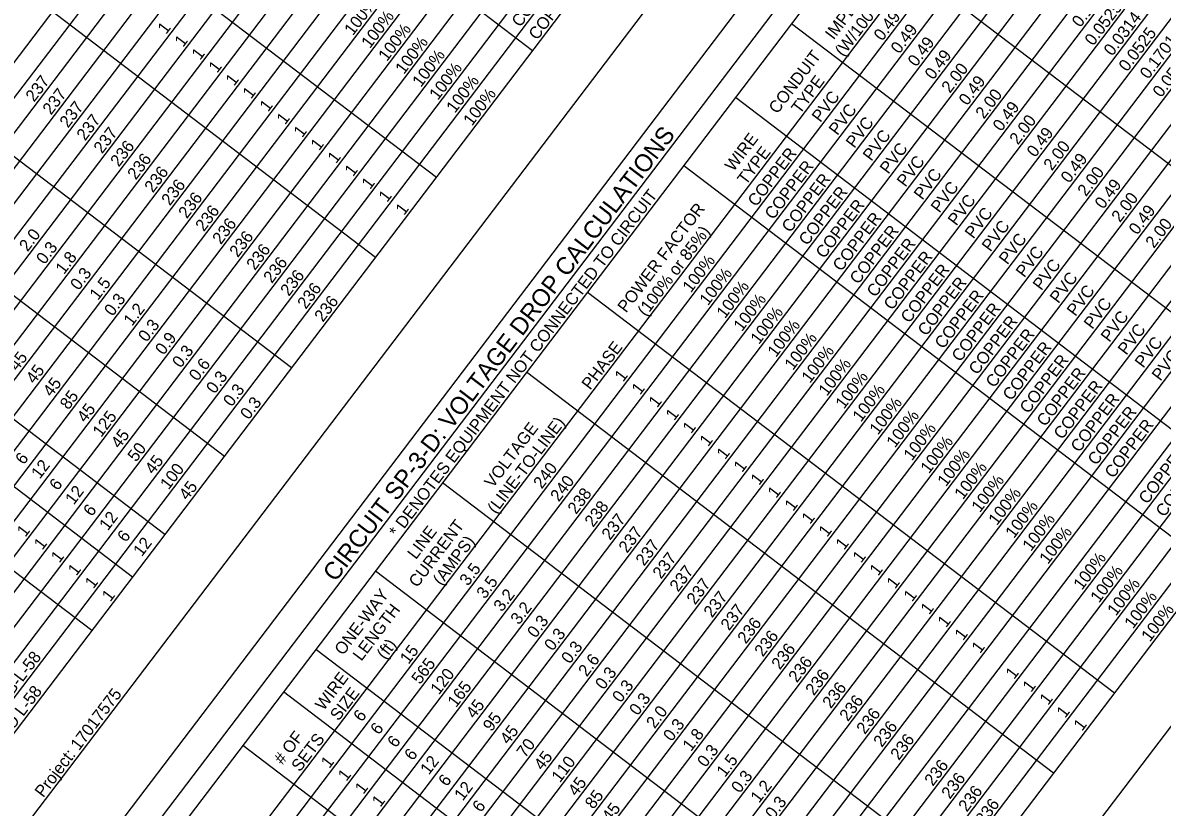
# Model space of a CAD drawing. Extents: x 1289840 to 1300285, y 220865 to 232461.
# Drawn here: x 1299156 to 1299781, y 231315 to 231745 of the extents above; entities that cross this region are included whole.
import ezdxf

# ---------------------------------------------------------------- set-up
doc = ezdxf.new("R2010")
doc.units = 0
doc.layers.add('Default', color=7, linetype='Continuous')

msp = doc.modelspace()

# ---------------------------------------------------------------- linework, layer by layer
at = {"layer": 'Default'}
for p, q in [((1298922.85, 231421.89), (1299441.25, 232103.62)), ((1298932.16, 231414.81), (1299450.56, 232096.54)), ((1298941.48, 231407.73), (1299459.87, 232089.46)), ((1298950.79, 231400.64), (1299469.19, 232082.37)), ((1298960.1, 231393.56), (1299478.5, 232075.29)), ((1298969.42, 231386.48), (1299487.81, 232068.21)), ((1298978.73, 231379.4), (1299497.13, 232061.13)), ((1298988.04, 231372.32), (1299506.44, 232054.05)), ((1298997.36, 231365.24), (1299515.75, 232046.96)), ((1299006.67, 231358.15), (1299525.07, 232039.88)), ((1299015.98, 231351.07), (1299534.38, 232032.8)), ((1299025.3, 231343.99), (1299543.69, 232025.72)), ((1299034.61, 231336.91), (1299553.01, 232018.64)), ((1299043.92, 231329.83), (1299562.32, 232011.55)), ((1299053.24, 231322.74), (1299571.63, 232004.47)), ((1299062.55, 231315.66), (1299580.95, 231997.39)), ((1299071.86, 231308.58), (1299590.26, 231990.31)), ((1299081.18, 231301.5), (1299599.57, 231983.23)), ((1299090.49, 231294.42), (1299608.89, 231976.15)), ((1299099.8, 231287.33), (1299618.2, 231969.06)), ((1299435.84, 231729.25), (1299137.82, 231955.87)), ((1299128.21, 231265.73), (1299646.6, 231947.46)), ((1299160.21, 231241.4), (1299678.61, 231923.13)), ((1299173.25, 231231.49), (1299691.64, 231913.21)), ((1299182.56, 231224.4), (1299700.96, 231906.13)), ((1299383.08, 231659.86), (1299085.05, 231886.49)), ((1299210.5, 231203.16), (1299728.9, 231884.89)), ((1299219.81, 231196.08), (1299738.21, 231877.8)), ((1299229.13, 231188.99), (1299747.52, 231870.72)), ((1299238.44, 231181.91), (1299756.84, 231863.64)), ((1299247.75, 231174.83), (1299766.15, 231856.56)), ((1299257.07, 231167.75), (1299775.46, 231849.48)), ((1299349.79, 231616.09), (1299051.77, 231842.71)), ((1299266.38, 231160.67), (1299784.78, 231842.4)), ((1299275.69, 231153.58), (1299794.09, 231835.31)), ((1299285.01, 231146.5), (1299803.4, 231828.23)), ((1299294.32, 231139.42), (1299812.72, 231821.15)), ((1299303.63, 231132.34), (1299822.03, 231814.07)), ((1299312.95, 231125.26), (1299831.34, 231806.99)), ((1299322.26, 231118.17), (1299840.66, 231799.9)), ((1299905.04, 231575.3), (1299616.33, 231794.84)), ((1299331.57, 231111.09), (1299849.97, 231792.82)), ((1299303.76, 231555.56), (1299005.74, 231782.18)), ((1299340.89, 231104.01), (1299859.28, 231785.74)), ((1299350.2, 231096.93), (1299868.6, 231778.66)), ((1299359.51, 231089.85), (1299877.91, 231771.58)), ((1299368.83, 231082.77), (1299887.22, 231764.49)), ((1299378.14, 231075.68), (1299896.54, 231757.41)), ((1299387.45, 231068.6), (1299905.85, 231750.33)), ((1299396.77, 231061.52), (1299915.16, 231743.25)), ((1299866.44, 231524.54), (1299577.73, 231744.08)), ((1299266.94, 231507.13), (1298968.91, 231733.75)), ((1299406.08, 231054.44), (1299924.47, 231736.17)), ((1299415.39, 231047.36), (1299933.79, 231729.08)), ((1299424.7, 231040.27), (1299943.1, 231722)), ((1299434.02, 231033.19), (1299952.41, 231714.92)), ((1299443.33, 231026.11), (1299961.73, 231707.84)), ((1299835.64, 231484.03), (1299546.93, 231703.57)), ((1299452.64, 231019.03), (1299971.04, 231700.76)), ((1299234.36, 231464.29), (1298936.33, 231690.91)), ((1299461.96, 231011.95), (1299980.35, 231693.67)), ((1299471.27, 231004.86), (1299989.67, 231686.59)), ((1299216.65, 231441), (1298918.63, 231667.62)), ((1299499.68, 230983.26), (1300018.07, 231664.99)), ((1299807.31, 231446.78), (1299518.6, 231666.32)), ((1299194.35, 231411.67), (1298896.32, 231638.29)), ((1299754.55, 231377.39), (1299465.84, 231596.93)), ((1299721.26, 231333.62), (1299432.55, 231553.16)), ((1299675.23, 231273.09), (1299386.52, 231492.62)), ((1299638.4, 231224.66), (1299349.69, 231444.2)), ((1299605.83, 231181.82), (1299317.12, 231401.35)), ((1299588.12, 231158.53), (1299299.41, 231378.07)), ((1299565.81, 231129.2), (1299277.1, 231348.74))]:
    msp.add_line(p, q, dxfattribs=at)

# ---------------------------------------------------------------- texts
for s, height, p in [('IMPEDANCE', 6.6, (1299600.72, 231734.86)), ('COPPER', 6.6, (1299428.99, 231741.75)), ('COPPER', 6.6, (1299438.3, 231734.67)), ('0.1801', 6.6, (1299735.89, 231741.63)), ('100%', 6.6, (1299337.35, 231737.21)), ('(W/1000 ft)', 6.6, (1299606.11, 231725.6)), ('0.0525', 6.6, (1299742.94, 231731.57)), ('100%', 6.6, (1299346.66, 231730.13)), ('0.49', 6.6, (1299627.37, 231734.22)), ('0.0314', 6.6, (1299753.38, 231725.97)), ('1', 6.6, (1299235, 231737.92)), ('100%', 6.6, (1299355.98, 231723.05)), ('0.49', 6.6, (1299636.68, 231727.14)), ('0.0525', 6.6, (1299761.56, 231717.4)), ('1', 6.6, (1299244.31, 231730.84)), ('100%', 6.6, (1299365.29, 231715.97)), ('0.49', 6.6, (1299645.99, 231720.05)), ('0.1701', 6.6, (1299773.14, 231713.3)), ('1', 6.6, (1299253.63, 231723.76)), ('100%', 6.6, (1299374.6, 231708.89)), ('CONDUIT', 6.6, (1299569.84, 231694.25)), ('0.49', 6.6, (1299655.31, 231712.97)), ('0.0525', 6.6, (1299780.19, 231703.24)), ('1', 6.6, (1299262.94, 231716.68)), ('100%', 6.6, (1299383.91, 231701.8)), ('2.00', 6.6, (1299664.46, 231705.68)), ('237', 6.6, (1299162.68, 231700.81)), ('1', 6.6, (1299272.25, 231709.6)), ('100%', 6.6, (1299393.23, 231694.72)), ('TYPE', 6.6, (1299582.23, 231694.2)), ('0.49', 6.6, (1299673.93, 231698.81)), ('237', 6.6, (1299172, 231693.73)), ('1', 6.6, (1299281.57, 231702.51)), ('100%', 6.6, (1299402.54, 231687.64)), ('2.00', 6.6, (1299683.09, 231691.52)), ('237', 6.6, (1299181.31, 231686.65)), ('1', 6.6, (1299290.88, 231695.43)), ('PVC', 6.6, (1299593.45, 231689.62)), ('0.49', 6.6, (1299692.56, 231684.64)), ('237', 6.6, (1299190.62, 231679.56)), ('1', 6.6, (1299300.19, 231688.35)), ('PVC', 6.6, (1299602.76, 231682.53)), ('PVC', 6.6, (1299612.08, 231675.45)), ('2.00', 6.6, (1299701.71, 231677.35)), ('237', 6.6, (1299199.94, 231672.48)), ('1', 6.6, (1299309.51, 231681.27)), ('CIRCUIT SP-3-D: VOLTAGE DROP CALCULATIONS', 9.6, (1299327.79, 231437.89)), ('WIRE', 6.6, (1299545.86, 231662.71)), ('PVC', 6.6, (1299621.39, 231668.37)), ('0.49', 6.6, (1299711.18, 231670.48)), ('236', 6.6, (1299209.14, 231665.26)), ('1', 6.6, (1299318.82, 231674.19)), ('TYPE', 6.6, (1299552.67, 231655.31)), ('COPPER', 6.6, (1299558.32, 231643.41)), ('PVC', 6.6, (1299630.7, 231661.29)), ('2.00', 6.6, (1299720.34, 231663.19)), ('236', 6.6, (1299218.45, 231658.17)), ('1', 6.6, (1299328.13, 231667.1)), ('PVC', 6.6, (1299640.02, 231654.21)), ('0.49', 6.6, (1299729.81, 231656.32)), ('236', 6.6, (1299227.77, 231651.09)), ('1', 6.6, (1299337.45, 231660.02)), ('COPPER', 6.6, (1299567.63, 231636.33)), ('PVC', 6.6, (1299649.33, 231647.12)), ('2.00', 6.6, (1299738.97, 231649.03)), ('236', 6.6, (1299237.08, 231644.01)), ('1', 6.6, (1299346.76, 231652.94)), ('COPPER', 6.6, (1299576.94, 231629.25)), ('PVC', 6.6, (1299658.64, 231640.04)), ('0.49', 6.6, (1299748.44, 231642.15)), ('236', 6.6, (1299246.39, 231636.93)), ('1', 6.6, (1299356.07, 231645.86)), ('* DENOTES EQUIPMENT NOT CONNECTED TO CIRCUIT', 6.6, (1299361.83, 231462.34)), ('COPPER', 6.6, (1299586.26, 231622.17)), ('2.00', 6.6, (1299757.59, 231634.86)), ('236', 6.6, (1299255.71, 231629.85)), ('1', 6.6, (1299365.39, 231638.78)), ('POWER FACTOR ', 6.6, (1299487.02, 231585.34)), ('COPPER', 6.6, (1299595.57, 231615.08)), ('PVC', 6.6, (1299667.96, 231632.96)), ('COPPER', 6.6, (1299604.88, 231608)), ('PVC', 6.6, (1299677.27, 231625.88)), ('0.49', 6.6, (1299767.06, 231627.99)), ('236', 6.6, (1299265.02, 231622.76)), ('(100% or 85%)', 6.6, (1299497.91, 231583.3)), ('COPPER', 6.6, (1299614.2, 231600.92)), ('PVC', 6.6, (1299686.58, 231618.8)), ('2.00', 6.6, (1299776.22, 231620.7)), ('2.0', 6.6, (1299159.15, 231618.85)), ('236', 6.6, (1299274.33, 231615.68)), ('COPPER', 6.6, (1299623.51, 231593.84)), ('PVC', 6.6, (1299695.9, 231611.72)), ('0.3', 6.6, (1299168.48, 231611.79)), ('236', 6.6, (1299283.65, 231608.6)), ('PVC', 6.6, (1299705.21, 231604.63)), ('1.8', 6.6, (1299179.08, 231606.4)), ('236', 6.6, (1299292.96, 231601.52)), ('100%', 6.6, (1299522.55, 231596.38)), ('COPPER', 6.6, (1299632.82, 231586.76)), ('PVC', 6.6, (1299714.52, 231597.55)), ('0.3', 6.6, (1299187.11, 231597.62)), ('236', 6.6, (1299302.27, 231594.44)), ('100%', 6.6, (1299531.87, 231589.3)), ('COPPER', 6.6, (1299642.13, 231579.67)), ('PVC', 6.6, (1299723.84, 231590.47)), ('1.5', 6.6, (1299197.71, 231592.24)), ('236', 6.6, (1299311.58, 231587.35)), ('100%', 6.6, (1299541.18, 231582.22)), ('COPPER', 6.6, (1299651.45, 231572.59)), ('0.3', 6.6, (1299205.73, 231583.46)), ('236', 6.6, (1299320.9, 231580.27)), ('100%', 6.6, (1299550.49, 231575.14)), ('COPPER', 6.6, (1299660.76, 231565.51)), ('PVC', 6.6, (1299733.15, 231583.39)), ('1.2', 6.6, (1299216.34, 231578.07)), ('100%', 6.6, (1299559.81, 231568.05)), ('COPPER', 6.6, (1299670.07, 231558.43)), ('PVC', 6.6, (1299742.46, 231576.31)), ('COPPER', 6.6, (1299679.39, 231551.35)), ('PVC', 6.6, (1299751.78, 231569.22)), ('0.3', 6.6, (1299224.36, 231569.3)), ('100%', 6.6, (1299569.12, 231560.97)), ('COPPER', 6.6, (1299688.7, 231544.26)), ('PVC', 6.6, (1299761.09, 231562.14)), ('0.9', 6.6, (1299233.66, 231562.19)), ('PHASE', 6.6, (1299467.34, 231543.1)), ('100%', 6.6, (1299578.43, 231553.89)), ('PVC', 6.6, (1299770.4, 231555.06)), ('45', 6.6, (1299153.54, 231553.48)), ('0.3', 6.6, (1299242.99, 231555.13)), ('100%', 6.6, (1299587.75, 231546.81)), ('COPPER', 6.6, (1299698.01, 231537.18)), ('PVC', 6.6, (1299779.72, 231547.98)), ('45', 6.6, (1299162.85, 231546.4)), ('0.6', 6.6, (1299252.19, 231547.9)), ('100%', 6.6, (1299597.06, 231539.73)), ('COPPER', 6.6, (1299707.33, 231530.1)), ('0.3', 6.6, (1299261.61, 231540.97)), ('1', 6.6, (1299485.4, 231547.52)), ('100%', 6.6, (1299606.37, 231532.64)), ('COPPER', 6.6, (1299716.64, 231523.02)), ('45', 6.6, (1299172.16, 231539.31)), ('0.3', 6.6, (1299270.93, 231533.89)), ('1', 6.6, (1299494.71, 231540.44)), ('100%', 6.6, (1299615.69, 231525.56)), ('COPPER', 6.6, (1299725.95, 231515.94)), ('85', 6.6, (1299181.48, 231532.23)), ('0.3', 6.6, (1299280.24, 231526.8)), ('1', 6.6, (1299504.02, 231533.35)), ('100%', 6.6, (1299625, 231518.48)), ('COPPER', 6.6, (1299735.27, 231508.86)), ('45', 6.6, (1299190.79, 231525.15)), ('125', 6.6, (1299199.44, 231517.2)), ('1', 6.6, (1299513.34, 231526.27)), ('COPPER', 6.6, (1299744.58, 231501.77)), ('VOLTAGE ', 6.6, (1299414.04, 231489.37)), ('(LINE-TO-LINE)', 6.6, (1299415.7, 231475.19)), ('100%', 6.6, (1299634.31, 231511.4)), ('COPPER', 6.6, (1299753.89, 231494.69)), ('45', 6.6, (1299209.42, 231510.99)), ('1', 6.6, (1299522.65, 231519.19)), ('100%', 6.6, (1299643.63, 231504.32)), ('50', 6.6, (1299218.56, 231503.68)), ('1', 6.6, (1299531.96, 231512.11)), ('100%', 6.6, (1299652.94, 231497.23)), ('6', 6.6, (1299157.04, 231502.13)), ('45', 6.6, (1299228.04, 231496.82)), ('1', 6.6, (1299541.28, 231505.03)), ('100%', 6.6, (1299662.25, 231490.15)), ('COPPER', 6.6, (1299772.52, 231480.53)), ('12', 6.6, (1299165.8, 231494.32)), ('100', 6.6, (1299236.37, 231488.44)), ('240', 6.6, (1299440.85, 231488.93)), ('1', 6.6, (1299550.59, 231497.94)), ('100%', 6.6, (1299671.56, 231483.07)), ('COPPER', 6.6, (1299781.83, 231473.45)), ('6', 6.6, (1299175.67, 231487.96)), ('240', 6.6, (1299450.16, 231481.85)), ('1', 6.6, (1299559.9, 231490.86)), ('100%', 6.6, (1299680.88, 231475.99)), ('12', 6.6, (1299184.43, 231480.16)), ('45', 6.6, (1299246.67, 231482.66)), ('238', 6.6, (1299459.65, 231475)), ('1', 6.6, (1299569.22, 231483.78)), ('100%', 6.6, (1299690.19, 231468.91)), ('238', 6.6, (1299468.96, 231467.91)), ('1', 6.6, (1299578.53, 231476.7)), ('100%', 6.6, (1299699.5, 231461.82)), ('6', 6.6, (1299194.29, 231473.8)), ('12', 6.6, (1299203.06, 231465.99)), ('237', 6.6, (1299478.27, 231460.83)), ('CURRENT ', 6.6, (1299372.6, 231434.86)), ('1', 6.6, (1299587.84, 231469.62)), ('100%', 6.6, (1299708.82, 231454.74)), ('1', 6.6, (1299157.88, 231462.54)), ('6', 6.6, (1299212.92, 231459.64)), ('LINE ', 6.6, (1299371.87, 231450.27)), ('237', 6.6, (1299487.59, 231453.75)), ('1', 6.6, (1299597.16, 231462.54)), ('100%', 6.6, (1299718.13, 231447.66)), ('1', 6.6, (1299167.2, 231455.46)), ('12', 6.6, (1299221.68, 231451.83)), ('(AMPS)', 6.6, (1299385.84, 231435.93)), ('237', 6.6, (1299496.9, 231446.67)), ('1', 6.6, (1299606.47, 231455.45)), ('1', 6.6, (1299176.51, 231448.38)), ('237', 6.6, (1299506.21, 231439.59)), ('1', 6.6, (1299615.78, 231448.37)), ('100%', 6.6, (1299736.76, 231433.5)), ('1', 6.6, (1299185.82, 231441.3)), ('3.5', 6.6, (1299400.41, 231435.75)), ('237', 6.6, (1299515.53, 231432.5)), ('1', 6.6, (1299625.1, 231441.29)), ('100%', 6.6, (1299746.07, 231426.42)), ('1', 6.6, (1299195.14, 231434.22)), ('3.5', 6.6, (1299409.72, 231428.67)), ('237', 6.6, (1299524.84, 231425.42)), ('1', 6.6, (1299634.41, 231434.21)), ('100%', 6.6, (1299755.38, 231419.33)), ('1', 6.6, (1299204.45, 231427.13)), ('ONE-WAY', 6.6, (1299331.92, 231397.73)), ('3.2', 6.6, (1299419.04, 231421.59)), ('237', 6.6, (1299534.15, 231418.34)), ('1', 6.6, (1299643.72, 231427.13)), ('100%', 6.6, (1299764.7, 231412.25)), ('LENGTH', 6.6, (1299341.97, 231394.59)), ('3.2', 6.6, (1299428.35, 231414.51)), ('237', 6.6, (1299543.47, 231411.26)), ('1', 6.6, (1299653.04, 231420.04)), ('0.3', 6.6, (1299437.5, 231407.22)), ('100%', 6.6, (1299774.01, 231405.17)), ('236', 6.6, (1299552.67, 231404.03)), ('1', 6.6, (1299662.35, 231412.96)), ('0.3', 6.6, (1299446.82, 231400.14)), ('236', 6.6, (1299561.98, 231396.95)), ('1', 6.6, (1299671.66, 231405.88)), ('(ft)', 6.6, (1299355.04, 231395.42)), ('15', 6.6, (1299367.81, 231392.89)), ('0.3', 6.6, (1299456.13, 231393.05)), ('236', 6.6, (1299571.3, 231389.87)), ('1', 6.6, (1299680.98, 231398.8)), ('PB-L-59 TO PB-L-58', 6.6, (1299117.41, 231332)), ('565', 6.6, (1299374.11, 231381.84)), ('2.6', 6.6, (1299465.49, 231386.03)), ('236', 6.6, (1299580.61, 231382.79)), ('WIRE', 6.6, (1299321.36, 231367.48)), ('120', 6.6, (1299384.48, 231376.14)), ('0.3', 6.6, (1299474.76, 231378.89)), ('236', 6.6, (1299589.92, 231375.7)), ('1', 6.6, (1299699.6, 231384.63)), ('165', 6.6, (1299393.87, 231369.16)), ('0.3', 6.6, (1299484.07, 231371.81)), ('236', 6.6, (1299599.23, 231368.62)), ('1', 6.6, (1299708.91, 231377.55)), ('PB-L-58 TO L-58', 6.6, (1299126.72, 231324.92)), ('Project: 17017575', 6.6, (1299167.71, 231319.86)), ('SIZE', 6.6, (1299329.49, 231361.82)), ('0.3', 6.6, (1299493.38, 231364.73)), ('236', 6.6, (1299608.55, 231361.54)), ('1', 6.6, (1299718.23, 231370.47)), ('45', 6.6, (1299403.94, 231363.07)), ('2.0', 6.6, (1299502.68, 231357.62)), ('6', 6.6, (1299342.25, 231361.3)), ('95', 6.6, (1299413.25, 231355.99)), ('236', 6.6, (1299617.86, 231354.46)), ('1', 6.6, (1299727.54, 231363.39)), ('6', 6.6, (1299351.56, 231354.21)), ('45', 6.6, (1299422.56, 231348.91)), ('0.3', 6.6, (1299512.01, 231350.56)), ('1.8', 6.6, (1299522.61, 231345.18)), ('236', 6.6, (1299627.17, 231347.38)), ('1', 6.6, (1299736.85, 231356.31)), ('# OF ', 6.6, (1299298.79, 231337.8)), ('SETS', 6.6, (1299308.29, 231333.94)), ('6', 6.6, (1299360.87, 231347.13)), ('70', 6.6, (1299431.7, 231341.6)), ('236', 6.6, (1299636.49, 231340.29)), ('6', 6.6, (1299370.19, 231340.05)), ('45', 6.6, (1299441.19, 231334.74)), ('0.3', 6.6, (1299530.64, 231336.4)), ('1', 6.6, (1299324.46, 231335.87)), ('12', 6.6, (1299378.95, 231332.24)), ('110', 6.6, (1299450.8, 231328.06)), ('1.5', 6.6, (1299541.24, 231331.01)), ('236', 6.6, (1299655.11, 231326.13)), ('1', 6.6, (1299333.77, 231328.79)), ('6', 6.6, (1299388.81, 231325.89)), ('0.3', 6.6, (1299549.26, 231322.23)), ('236', 6.6, (1299664.43, 231319.05)), ('1', 6.6, (1299343.09, 231321.71)), ('12', 6.6, (1299397.57, 231318.08)), ('45', 6.6, (1299459.81, 231320.58)), ('1.2', 6.6, (1299559.87, 231316.85)), ('236', 6.6, (1299673.74, 231311.97)), ('1', 6.6, (1299352.4, 231314.63)), ('85', 6.6, (1299469.13, 231313.5)), ('0.3', 6.6, (1299567.89, 231308.07)), ('6', 6.6, (1299407.44, 231311.72)), ('45', 6.6, (1299478.44, 231306.42)), ('236', 6.6, (1299683.05, 231304.88))]:
    msp.add_text(s, height=height, rotation=52.75013, dxfattribs=at).set_placement(p)

doc.saveas('drawing.dxf')
